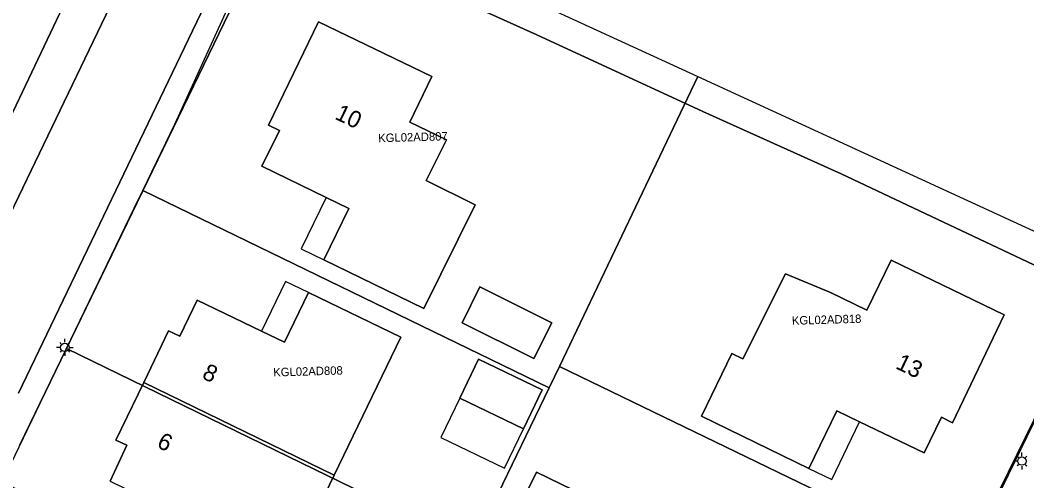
# Model space of a CAD drawing. Extents: x 124901 to 125496, y 515369 to 515789.
# Drawn here: x 125282.1 to 125341.9, y 515725.2 to 515752.5 of the extents above; entities that cross this region are included whole.
import ezdxf

# ---------------------------------------------------------------- set-up
doc = ezdxf.new("R2010")
doc.units = 0
for name, color, linetype in [('Gebouw', 7, 'Continuous'), ('Lichtmast', 7, 'Continuous'), ('Luifel', 7, 'Continuous'), ('Onbegroeid terrein', 7, 'Continuous'), ('Parkeren', 7, 'Continuous'), ('Perceelnummers', 7, 'Continuous'), ('Perceelsgrenzen', 7, 'Continuous'), ('Teksten', 7, 'Continuous'), ('Vegetatie', 7, 'Continuous'), ('Voetpad', 7, 'Continuous'), ('Water', 7, 'Continuous'), ('Wegen lokale weg', 7, 'Continuous')]:
    doc.layers.add(name, color=color, linetype=linetype)

msp = doc.modelspace()

# ---------------------------------------------------------------- linework, layer by layer
at = {"layer": 'Gebouw'}
for points in [[(125306.56, 515749.18), (125299.82, 515752.41), (125296.85, 515746.29), (125297.508, 515745.968), (125296.47, 515743.85), (125300.274, 515742.006), (125301.624, 515741.352), (125300.151, 515738.303), (125306.089, 515735.424), (125309.133, 515741.56), (125306.222, 515743.004), (125307.42, 515745.42), (125305.25, 515746.468)], [(125332.39, 515735.309), (125330.229, 515736.356), (125327.562, 515737.462), (125325.027, 515732.429), (125324.366, 515732.749), (125322.559, 515729.021), (125328.95, 515725.93), (125330.598, 515729.354), (125331.95, 515728.703), (125335.78, 515726.86), (125336.817, 515728.962), (125337.47, 515728.64), (125340.54, 515735.03), (125333.83, 515738.28)], [(125312.613, 515732.44), (125313.673, 515734.56), (125309.411, 515736.691), (125308.351, 515734.572)], [(125304.715, 515733.707), (125299.224, 515736.361), (125297.799, 515733.41), (125296.448, 515734.061), (125292.63, 515735.9), (125291.589, 515733.768), (125290.93, 515734.09), (125289.453, 515731.033), (125300.762, 515725.529)], [(125313.109, 515730.591), (125309.326, 515732.407), (125308.219, 515730.101), (125312.002, 515728.284)], [(125288.453, 515727.301), (125287.45, 515725.18), (125291.276, 515723.318), (125292.625, 515722.662), (125291.43, 515720.206), (125296.903, 515717.543), (125300.762, 515725.529), (125289.453, 515731.033), (125287.8, 515727.61)], [(125311.83, 515723.786), (125314.696, 515722.401), (125315.63, 515724.33), (125312.767, 515725.708)]]:
    msp.add_lwpolyline(points, close=True, dxfattribs=at)
at = {"layer": 'Lichtmast'}
for p, q in [((125284.769, 515733.408), (125284.769, 515733.608)), ((125284.469, 515733.109), (125284.269, 515733.108)), ((125284.557, 515732.896), (125284.485, 515732.825)), ((125284.557, 515733.32), (125284.487, 515733.391)), ((125284.769, 515732.808), (125284.769, 515732.608)), ((125284.981, 515733.32), (125285.052, 515733.392)), ((125284.981, 515732.896), (125285.051, 515732.825)), ((125285.069, 515733.108), (125285.269, 515733.108)), ((125341.594, 515726.665), (125341.594, 515726.865)), ((125341.294, 515726.366), (125341.094, 515726.365)), ((125341.382, 515726.577), (125341.312, 515726.648)), ((125341.806, 515726.577), (125341.877, 515726.649)), ((125341.382, 515726.153), (125341.31, 515726.082)), ((125341.594, 515726.065), (125341.594, 515725.865)), ((125341.806, 515726.153), (125341.876, 515726.082))]:
    msp.add_line(p, q, dxfattribs=at)
for centre in [(125284.769, 515733.108), (125341.594, 515726.365)]:
    msp.add_circle(centre, 0.25, dxfattribs=at)
at = {"layer": 'Luifel'}
for points in [[(125301.624, 515741.352), (125300.274, 515742.006), (125298.8, 515738.956), (125300.151, 515738.303)], [(125296.448, 515734.061), (125297.799, 515733.41), (125299.224, 515736.361), (125297.873, 515737.013)], [(125308.219, 515730.101), (125307.096, 515727.764), (125310.879, 515725.947), (125312.002, 515728.284)], [(125330.598, 515729.354), (125328.95, 515725.93), (125330.302, 515725.279), (125331.95, 515728.703)]]:
    msp.add_lwpolyline(points, close=True, dxfattribs=at)
at = {"layer": 'Onbegroeid terrein'}
for points in [[(125345.865, 515736.317), (125330.851, 515743.393), (125322.639, 515747.097), (125312.784, 515751.645), (125298.192, 515758.231)], [(125296.354, 515756.747), (125282.093, 515727.334)], [(125287.45, 515725.18), (125288.453, 515727.301), (125287.8, 515727.61), (125289.453, 515731.033), (125290.93, 515734.09), (125291.589, 515733.768), (125292.63, 515735.9), (125296.448, 515734.061), (125297.799, 515733.41), (125299.224, 515736.361), (125304.715, 515733.707), (125300.762, 515725.529), (125296.903, 515717.543)], [(125340.408, 515724.765), (125346.002, 515736.243)]]:
    msp.add_lwpolyline(points, dxfattribs=at)
for points in [[(125299.82, 515752.41), (125306.56, 515749.18), (125305.25, 515746.468), (125307.42, 515745.42), (125306.222, 515743.004), (125309.133, 515741.56), (125306.089, 515735.424), (125300.151, 515738.303), (125301.624, 515741.352), (125300.274, 515742.006), (125296.47, 515743.85), (125297.508, 515745.968), (125296.85, 515746.29)], [(125330.229, 515736.356), (125332.39, 515735.309), (125333.83, 515738.28), (125340.54, 515735.03), (125337.47, 515728.64), (125336.817, 515728.962), (125335.78, 515726.86), (125331.95, 515728.703), (125330.598, 515729.354), (125328.95, 515725.93), (125322.559, 515729.021), (125324.366, 515732.749), (125325.027, 515732.429), (125327.562, 515737.462)], [(125313.673, 515734.56), (125312.613, 515732.44), (125308.351, 515734.572), (125309.411, 515736.691)], [(125308.219, 515730.101), (125309.326, 515732.407), (125313.109, 515730.591), (125312.002, 515728.284)], [(125311.83, 515723.786), (125312.767, 515725.708), (125315.63, 515724.33), (125314.696, 515722.401), (125312.851, 515718.593), (125309.982, 515719.984)]]:
    msp.add_lwpolyline(points, close=True, dxfattribs=at)
at = {"layer": 'Parkeren'}
msp.add_lwpolyline([(125288.661, 515755.872), (125285.386, 515754.86), (125281.698, 515747.095), (125281.57, 515746.821), (125274.483, 515731.631), (125275.344, 515729.477), (125275.615, 515728.799)], close=True, dxfattribs=at)
at = {"layer": 'Perceelsgrenzen'}
for points in [[(125273.267, 515709.056), (125277.174, 515717.127), (125281.038, 515725.109), (125284.871, 515733.051), (125288.88, 515741.36), (125289.394, 515742.417), (125291.305, 515746.353), (125297.742, 515760.474), (125298.15, 515760.28), (125322.355, 515749.172), (125344.52, 515739), (125346.795, 515737.956), (125340.276, 515724.697), (125338.174, 515720.359), (125336.97, 515717.875), (125334.47, 515712.696), (125332.165, 515707.919), (125329.819, 515703.059), (125327.473, 515698.198), (125325.136, 515693.355), (125321.468, 515685.754), (125308.957, 515691.825), (125298.065, 515697.077), (125289.1, 515701.4)], [(125289.394, 515742.417), (125291.305, 515746.353), (125297.742, 515760.474), (125298.15, 515760.28), (125322.355, 515749.172), (125314.143, 515731.981), (125313.524, 515730.704)], [(125322.355, 515749.172), (125344.52, 515739), (125346.795, 515737.956), (125340.276, 515724.697), (125338.174, 515720.359), (125314.143, 515731.981)], [(125284.871, 515733.051), (125288.88, 515741.36), (125289.394, 515742.417), (125313.524, 515730.704), (125310.487, 515724.436), (125311.161, 515724.109), (125309.647, 515720.985)], [(125281.038, 515725.109), (125284.871, 515733.051), (125309.647, 515720.985), (125308.807, 515719.251), (125306.451, 515714.387), (125305.768, 515712.977)], [(125338.174, 515720.359), (125336.97, 515717.875), (125334.47, 515712.696), (125322.106, 515718.995), (125314.694, 515722.397), (125311.161, 515724.109), (125310.487, 515724.436), (125313.524, 515730.704), (125314.143, 515731.981)]]:
    msp.add_lwpolyline(points, close=True, dxfattribs=at)
at = {"layer": 'Vegetatie'}
msp.add_lwpolyline([(125275.615, 515728.799), (125275.344, 515729.477), (125274.483, 515731.631), (125281.57, 515746.821), (125281.698, 515747.095), (125285.386, 515754.86), (125288.661, 515755.872), (125289.873, 515758.156), (125284.966, 515760.475), (125272.159, 515734.076), (125268.062, 515725.6), (125268.777, 515725.42), (125269.164, 515725.351), (125270.088, 515725.317), (125271.12, 515725.395), (125271.975, 515725.619), (125273.146, 515726.148), (125273.784, 515726.591), (125274.019, 515726.754), (125274.716, 515727.37), (125275.164, 515727.991)], close=True, dxfattribs=at)
at = {"layer": 'Voetpad'}
for points in [[(125282.093, 515727.334), (125296.354, 515756.747), (125294.998, 515757.409), (125282.013, 515730.394)], [(125354.493, 515752.637), (125346.389, 515736.034), (125346.002, 515736.243), (125340.408, 515724.765), (125324.335, 515691.583), (125321.576, 515685.879), (125321.172, 515685.045), (125317.348, 515683.674), (125315.366, 515683.99), (125314.34, 515682.195)]]:
    msp.add_lwpolyline(points, dxfattribs=at)
at = {"layer": 'Water'}
msp.add_lwpolyline([(125301.033, 515766.831), (125298.192, 515758.231), (125312.784, 515751.645), (125322.639, 515747.097), (125330.851, 515743.393), (125345.865, 515736.317), (125352.897, 515750.85), (125345.657, 515754.42), (125341.384, 515756.505), (125294.863, 515779.172), (125293.879, 515779.651), (125292.865, 515780.145), (125284.865, 515784.043)], dxfattribs=at)
at = {"layer": 'Wegen lokale weg'}
msp.add_lwpolyline([(125282.013, 515730.394), (125294.998, 515757.409), (125290.539, 515759.585), (125289.873, 515758.156), (125288.661, 515755.872), (125275.615, 515728.799)], dxfattribs=at)

# ---------------------------------------------------------------- texts
at = {"layer": 'Perceelnummers'}
for s, rotation, p in [('KGL02AD807', 1.63341, (125303.38, 515745.27)), ('KGL02AD818', 1.6337, (125327.941, 515734.447)), ('KGL02AD808', 1.63334, (125297.148, 515731.382))]:
    msp.add_text(s, height=0.5, rotation=rotation, dxfattribs=at).set_placement(p)
at = {"layer": 'Teksten'}
for s, rotation, p in [('10', 334.1, (125300.737, 515746.686)), ('13', 334.3, (125334.036, 515731.886)), ('8', 334.2, (125292.855, 515731.301)), ('6', 334.2, (125290.172, 515727.216))]:
    msp.add_text(s, height=1, rotation=rotation, dxfattribs=at).set_placement(p)

doc.saveas('drawing.dxf')
